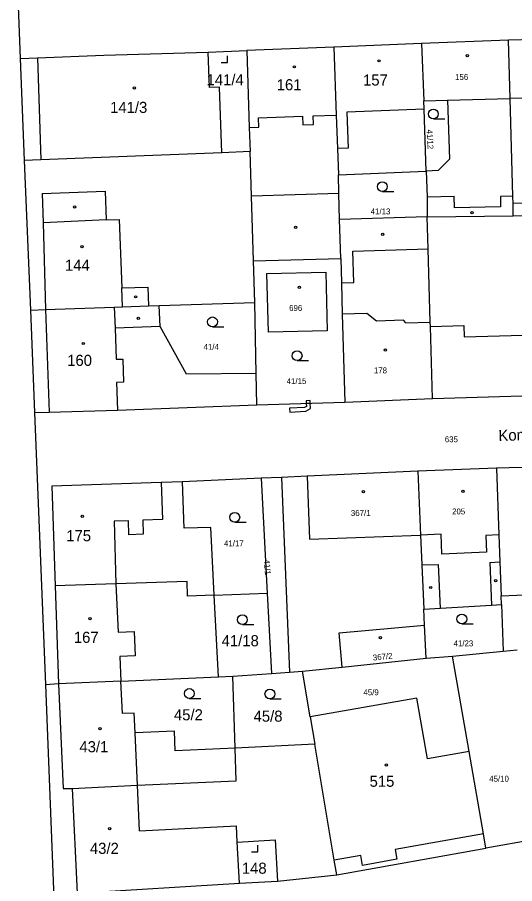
# Model space of a CAD drawing. Extents: x -758582 to -751794, y -998770 to -994350.
# Drawn here: x -755868.7 to -755792.6, y -995731.7 to -995599.1 of the extents above; entities that cross this region are included whole.
import ezdxf

# ---------------------------------------------------------------- set-up
doc = ezdxf.new("R2010")
doc.units = 0
for name, color, linetype in [('Hranice parcel', 7, 'Continuous'), ('Parcelní čísla', 7, 'Continuous'), ('Pop  PČ popisy', 7, 'Continuous'), ('Vnitřní kresba', 7, 'Continuous'), ('Věcná břemena k části', 7, 'Continuous'), ('Značky budov', 7, 'Continuous'), ('Značky kultur', 7, 'Continuous')]:
    doc.layers.add(name, color=color, linetype=linetype)

msp = doc.modelspace()

# ---------------------------------------------------------------- linework, layer by layer
at = {"layer": 'Hranice parcel'}
for p, q in [((-755868.68, -995594.4), (-755868.24, -995605.34)), ((-755793.5, -995602.57), (-755806.84, -995603.06)), ((-755780.18, -995602.19), (-755793.5, -995602.57)), ((-755839.46, -995604.38), (-755833.55, -995604.14)), ((-755820.24, -995603.65), (-755833.55, -995604.14)), ((-755806.84, -995603.06), (-755820.24, -995603.65)), ((-755806.84, -995603.06), (-755806.46, -995611.85)), ((-755868.24, -995605.34), (-755867.61, -995620.96)), ((-755833.06, -995619.62), (-755837.38, -995619.79)), ((-755867.61, -995620.96), (-755866.69, -995643.88)), ((-755819.55, -995623.2), (-755806.1, -995622.61)), ((-755805.96, -995629.63), (-755792.77, -995629.43)), ((-755792.77, -995629.43), (-755784.56, -995629.24)), ((-755805.96, -995629.63), (-755819.36, -995630.03)), ((-755819.19, -995636.01), (-755819.36, -995630.03)), ((-755832.54, -995636.35), (-755819.19, -995636.01)), ((-755832.34, -995642.73), (-755832.54, -995636.35)), ((-755846.95, -995643.2), (-755832.34, -995642.73)), ((-755832.12, -995653.59), (-755832.34, -995642.73)), ((-755866.69, -995643.88), (-755866.06, -995659.58)), ((-755832.02, -995658.39), (-755832.12, -995653.59)), ((-755832.02, -995658.39), (-755818.55, -995658)), ((-755818.55, -995658), (-755805.14, -995657.42)), ((-755866.06, -995659.58), (-755864.39, -995701.24)), ((-755782.88, -995667.7), (-755795.36, -995668.1)), ((-755824.32, -995669.32), (-755828.26, -995669.5)), ((-755807.39, -995668.55), (-755824.32, -995669.32)), ((-755795.36, -995668.1), (-755807.39, -995668.55)), ((-755807.39, -995668.55), (-755806.97, -995678.34)), ((-755831.35, -995669.64), (-755843.39, -995670.19)), ((-755828.26, -995669.5), (-755831.35, -995669.64)), ((-755831.35, -995669.64), (-755830.45, -995687.23)), ((-755828.26, -995669.5), (-755827.02, -995699.31)), ((-755862.9, -995686.1), (-755862.4, -995701.13)), ((-755838.54, -995687.54), (-755830.45, -995687.23)), ((-755837.88, -995700.03), (-755838.54, -995687.54)), ((-755830.45, -995687.23), (-755829.79, -995699.51)), ((-755794.58, -995688.97), (-755794.63, -995687.64)), ((-755794.58, -995688.97), (-755794.31, -995696.13)), ((-755806.1, -995697.2), (-755802.09, -995696.9)), ((-755802.09, -995696.9), (-755794.31, -995696.13)), ((-755799.54, -995711.49), (-755802.09, -995696.9)), ((-755794.31, -995696.13), (-755792.19, -995695.92)), ((-755835.71, -995699.93), (-755829.79, -995699.51)), ((-755829.79, -995699.51), (-755827.02, -995699.31)), ((-755827.02, -995699.31), (-755825.04, -995699.17)), ((-755823.86, -995706.17), (-755825.04, -995699.17)), ((-755862.4, -995701.13), (-755864.39, -995701.24)), ((-755852.83, -995700.7), (-755862.4, -995701.13)), ((-755852.83, -995700.7), (-755837.88, -995700.03)), ((-755837.88, -995700.03), (-755835.71, -995699.93)), ((-755835.35, -995710.94), (-755835.71, -995699.93)), ((-755823.86, -995706.17), (-755823.16, -995710.34)), ((-755823.16, -995710.34), (-755835.35, -995710.94)), ((-755770.99, -995721.69), (-755796.96, -995726.25)), ((-755819.8, -995730.35), (-755796.96, -995726.25)), ((-755834.67, -995731.62), (-755828.88, -995731.31)), ((-755828.88, -995731.31), (-755819.8, -995730.35))]:
    msp.add_line(p, q, dxfattribs=at)
for points in [[(-755792.77, -995629.43), (-755792.79, -995627.57), (-755792.82, -995626.44), (-755793.25, -995611.47), (-755793.5, -995602.57)], [(-755833.55, -995604.14), (-755833.18, -995615.94), (-755833.06, -995619.62)], [(-755820.24, -995603.65), (-755819.86, -995614.02), (-755819.67, -995619.14), (-755819.55, -995623.2)], [(-755868.24, -995605.34), (-755865.58, -995605.25), (-755855.42, -995604.85), (-755839.46, -995604.38)], [(-755837.38, -995619.79), (-755837.74, -995609.74), (-755839.26, -995609.79), (-755839.46, -995604.38)], [(-755806.46, -995611.85), (-755802.82, -995611.75), (-755802.53, -995620.78), (-755804.25, -995622.53), (-755806.1, -995622.61)], [(-755806.1, -995622.61), (-755806.4, -995613.12), (-755806.46, -995611.85)], [(-755837.38, -995619.79), (-755865.08, -995620.88), (-755867.61, -995620.96)], [(-755832.54, -995636.35), (-755832.85, -995626.45), (-755833.06, -995619.62)], [(-755806.1, -995622.61), (-755805.97, -995626.53), (-755805.96, -995629.63)], [(-755819.36, -995630.03), (-755819.47, -995626.04), (-755819.55, -995623.2)], [(-755805.14, -995657.42), (-755805.47, -995646.42), (-755805.49, -995645.72), (-755805.82, -995634.5), (-755805.96, -995629.63)], [(-755819.19, -995636.01), (-755819.08, -995639.69), (-755818.94, -995644.53), (-755818.55, -995658)], [(-755830.26, -995647.29), (-755830.51, -995638.29), (-755821.49, -995638.06), (-755821.26, -995647.05), (-755830.26, -995647.29)], [(-755866.69, -995643.88), (-755864.35, -995643.81), (-755853.85, -995643.44), (-755852.61, -995643.4), (-755848.61, -995643.26), (-755846.95, -995643.2)], [(-755832.12, -995653.59), (-755842.78, -995653.7), (-755846.83, -995646.39), (-755846.95, -995643.2)], [(-755805.14, -995657.42), (-755776.06, -995656.56), (-755772.87, -995656.44)], [(-755866.06, -995659.58), (-755863.8, -995659.5), (-755853.36, -995659.19), (-755832.02, -995658.39)], [(-755824.32, -995669.32), (-755823.96, -995678.98), (-755806.97, -995678.34)], [(-755795.36, -995668.1), (-755794.98, -995678.31), (-755794.82, -995682.45), (-755794.63, -995687.64)], [(-755843.39, -995670.19), (-755846.66, -995670.3), (-755863.41, -995670.84), (-755862.9, -995686.1)], [(-755838.54, -995687.54), (-755839.09, -995677.16), (-755843.14, -995677.29), (-755843.39, -995670.19)], [(-755806.97, -995678.34), (-755806.78, -995682.91), (-755806.49, -995689.68)], [(-755838.54, -995687.54), (-755842.65, -995687.7), (-755842.71, -995685.46), (-755853.59, -995685.79), (-755862.9, -995686.1)], [(-755794.63, -995687.64), (-755792.23, -995687.55), (-755782.12, -995686.92)], [(-755806.49, -995689.68), (-755803.9, -995689.52), (-755796.1, -995689.05), (-755794.58, -995688.97)], [(-755806.1, -995697.2), (-755806.39, -995692.13), (-755806.49, -995689.68)], [(-755825.04, -995699.17), (-755818.95, -995698.57), (-755806.1, -995697.2)], [(-755862.4, -995701.13), (-755861.68, -995717.14), (-755860.28, -995717.12)], [(-755835.35, -995710.94), (-755844.5, -995711.39), (-755844.64, -995708.35), (-755850.67, -995708.62), (-755850.81, -995705.59), (-755852.6, -995705.67), (-755852.83, -995700.7)], [(-755864.39, -995701.24), (-755863.02, -995735.23), (-755860.87, -995744.94)], [(-755799.54, -995711.49), (-755805.93, -995712.61), (-755807.56, -995703.31), (-755823.86, -995706.17)], [(-755819.8, -995730.35), (-755820.18, -995728.09), (-755823.16, -995710.34)], [(-755860.28, -995717.12), (-755850.31, -995716.65), (-755835.18, -995715.95), (-755835.35, -995710.94)], [(-755796.96, -995726.25), (-755797.34, -995724.09), (-755799.54, -995711.49)], [(-755860.28, -995717.12), (-755859.52, -995733.16), (-755834.67, -995731.62)], [(-755834.67, -995731.62), (-755835.01, -995725.33), (-755829.21, -995725.02), (-755828.88, -995731.31)]]:
    msp.add_lwpolyline(points, dxfattribs=at)
at = {"layer": 'Vnitřní kresba'}
for p, q in [((-755865.58, -995605.25), (-755865.08, -995620.88)), ((-755802.82, -995611.75), (-755793.25, -995611.47)), ((-755791.4, -995611.42), (-755793.25, -995611.47)), ((-755806.4, -995613.12), (-755818.24, -995613.56)), ((-755818.24, -995613.56), (-755818.04, -995619.08)), ((-755831.76, -995614.46), (-755825.04, -995614.21)), ((-755831.71, -995615.89), (-755831.76, -995614.46)), ((-755825.04, -995614.21), (-755825, -995615.52)), ((-755823.4, -995614.15), (-755819.86, -995614.02)), ((-755823.35, -995615.46), (-755823.4, -995614.15)), ((-755833.18, -995615.94), (-755831.71, -995615.89)), ((-755825, -995615.52), (-755823.35, -995615.46)), ((-755818.04, -995619.08), (-755819.67, -995619.14)), ((-755864.9, -995626.02), (-755855.23, -995625.68)), ((-755864.9, -995626.02), (-755864.75, -995630.53)), ((-755855.23, -995625.68), (-755855.07, -995630.07)), ((-755819.47, -995626.04), (-755832.85, -995626.45)), ((-755805.97, -995626.53), (-755801.8, -995626.44)), ((-755801.76, -995628.24), (-755801.8, -995626.44)), ((-755792.82, -995626.44), (-755794.75, -995626.48)), ((-755794.75, -995626.48), (-755794.71, -995628.08)), ((-755794.71, -995628.08), (-755801.76, -995628.24)), ((-755785.71, -995627.38), (-755792.79, -995627.57)), ((-755855.07, -995630.07), (-755864.75, -995630.53)), ((-755864.75, -995630.53), (-755864.35, -995643.81)), ((-755855.07, -995630.07), (-755853.07, -995630)), ((-755853.07, -995630), (-755852.71, -995640.5)), ((-755817.31, -995634.84), (-755805.82, -995634.5)), ((-755817.17, -995639.64), (-755817.31, -995634.84)), ((-755819.08, -995639.69), (-755817.17, -995639.64)), ((-755852.71, -995640.5), (-755848.71, -995640.36)), ((-755852.61, -995643.4), (-755852.71, -995640.5)), ((-755848.71, -995640.36), (-755848.61, -995643.26)), ((-755864.35, -995643.81), (-755863.8, -995659.5)), ((-755853.85, -995643.44), (-755853.73, -995646.64)), ((-755815.18, -995644.41), (-755818.94, -995644.53)), ((-755813.69, -995645.58), (-755815.18, -995644.41)), ((-755809.6, -995645.45), (-755813.69, -995645.58)), ((-755809.23, -995645.84), (-755809.6, -995645.45)), ((-755846.83, -995646.39), (-755853.73, -995646.64)), ((-755853.73, -995646.64), (-755853.55, -995651.42)), ((-755809.23, -995645.84), (-755805.49, -995645.72)), ((-755805.47, -995646.42), (-755800.32, -995646.27)), ((-755800.32, -995646.27), (-755800.27, -995647.97)), ((-755800.27, -995647.97), (-755781.38, -995647.41)), ((-755853.55, -995651.42), (-755852.55, -995651.38)), ((-755852.55, -995651.38), (-755852.42, -995654.93)), ((-755852.42, -995654.93), (-755853.52, -995654.97)), ((-755853.52, -995654.97), (-755853.36, -995659.19)), ((-755846.66, -995670.3), (-755846.48, -995675.97)), ((-755851.68, -995676.13), (-755853.88, -995676.19)), ((-755853.88, -995676.19), (-755853.59, -995685.79)), ((-755851.62, -995678.28), (-755851.68, -995676.13)), ((-755846.48, -995675.97), (-755849.48, -995676.06)), ((-755849.48, -995676.06), (-755849.42, -995678.21)), ((-755849.42, -995678.21), (-755851.62, -995678.28)), ((-755803.82, -995678.21), (-755806.97, -995678.34)), ((-755803.69, -995681.25), (-755803.82, -995678.21)), ((-755794.98, -995678.31), (-755796.98, -995678.4)), ((-755796.98, -995678.4), (-755796.87, -995680.96)), ((-755796.87, -995680.96), (-755803.69, -995681.25)), ((-755796.37, -995682.53), (-755794.82, -995682.45)), ((-755796.37, -995682.53), (-755796.1, -995689.05)), ((-755806.78, -995682.91), (-755804.22, -995682.82)), ((-755803.9, -995689.52), (-755804.22, -995682.82)), ((-755853.59, -995685.79), (-755853.25, -995693.22)), ((-755853.25, -995693.22), (-755850.8, -995693.11)), ((-755850.8, -995693.11), (-755850.63, -995696.8)), ((-755819.42, -995693.3), (-755806.39, -995692.13)), ((-755818.95, -995698.57), (-755819.42, -995693.3)), ((-755850.63, -995696.8), (-755853, -995696.91)), ((-755853, -995696.91), (-755852.83, -995700.7)), ((-755850.31, -995716.65), (-755850.67, -995708.62)), ((-755849.99, -995723.6), (-755850.31, -995716.65)), ((-755849.99, -995723.6), (-755835.14, -995722.84)), ((-755835.01, -995725.33), (-755835.14, -995722.84)), ((-755797.34, -995724.09), (-755810.85, -995726.46)), ((-755816.11, -995727.38), (-755820.18, -995728.09)), ((-755815.84, -995728.91), (-755816.11, -995727.38)), ((-755810.85, -995726.46), (-755810.58, -995727.98)), ((-755810.58, -995727.98), (-755815.84, -995728.91))]:
    msp.add_line(p, q, dxfattribs=at)
at = {"layer": 'Věcná břemena k části'}
for points in [[(-755824.45, -995658.17), (-755824.41, -995658.63), (-755824.71, -995658.78), (-755827.01, -995658.91), (-755826.97, -995659.51), (-755824.55, -995659.38), (-755823.79, -995658.97), (-755823.85, -995658.15)], [(-755823.85, -995658.15), (-755823.88, -995657.74), (-755824.48, -995657.76), (-755824.45, -995658.17)]]:
    msp.add_lwpolyline(points, close=True, dxfattribs=at)
at = {"layer": 'Značky budov'}
for centre in [(-755813.31, -995605.72), (-755799.81, -995604.93), (-755826.28, -995606.64), (-755850.77, -995609.88), (-755859.92, -995628.09), (-755799.08, -995628.96), (-755826.09, -995631.21), (-755812.76, -995632.29), (-755858.8, -995634.18), (-755825.5, -995640.41), (-755850.59, -995641.86), (-755850.17, -995645.14), (-755858.6, -995649), (-755812.35, -995650.01), (-755815.72, -995671.68), (-755800.48, -995671.63), (-755858.75, -995675.45), (-755795.48, -995685.3), (-755805.41, -995686.36), (-755857.58, -995691.14), (-755813.12, -995694.05), (-755856.02, -995707.97), (-755812.2, -995713.52), (-755854.54, -995723.28)]:
    msp.add_circle(centre, 0.175, dxfattribs=at)
at = {"layer": 'Značky kultur'}
for p, q in [((-755836.49, -995605.97), (-755836.49, -995604.97)), ((-755837.49, -995605.97), (-755836.49, -995605.97)), ((-755805.01, -995614.61), (-755803.26, -995614.61)), ((-755812.82, -995625.73), (-755811.07, -995625.73)), ((-755838.81, -995646.44), (-755837.06, -995646.44)), ((-755825.86, -995651.62), (-755824.11, -995651.62)), ((-755835.4, -995676.36), (-755833.65, -995676.36)), ((-755834.23, -995692.05), (-755832.48, -995692.05)), ((-755800.65, -995691.94), (-755798.9, -995691.94)), ((-755842.37, -995703.34), (-755840.62, -995703.34)), ((-755830.03, -995703.41), (-755828.28, -995703.41)), ((-755831.86, -995726.83), (-755831.86, -995725.83)), ((-755832.86, -995726.83), (-755831.86, -995726.83))]:
    msp.add_line(p, q, dxfattribs=at)
for centre in [(-755805.01, -995613.86), (-755812.82, -995624.98), (-755838.81, -995645.69), (-755825.86, -995650.87), (-755835.4, -995675.61), (-755834.23, -995691.3), (-755800.65, -995691.19), (-755842.37, -995702.59), (-755830.03, -995702.66)]:
    msp.add_circle(centre, 0.75, dxfattribs=at)

# ---------------------------------------------------------------- texts
at = {"layer": 'Parcelní čísla'}
for s, height, p in [('141/4', 1.7, (-755839.72, -995609.47)), ('157', 1.7, (-755815.77, -995609.51)), ('156', 0.9, (-755801.68, -995608.65)), ('161', 1.7, (-755828.98, -995610.23)), ('141/3', 1.7, (-755854.48, -995613.7)), ('41/13', 0.9, (-755814.6, -995629.23)), ('144', 1.7, (-755861.39, -995637.86)), ('696', 0.9, (-755827.08, -995644.02)), ('41/4', 0.9, (-755840.18, -995649.97)), ('160', 1.7, (-755861.05, -995652.43)), ('178', 0.9, (-755814.11, -995653.57)), ('41/15', 0.9, (-755827.46, -995655.21)), ('635', 0.9, (-755803.26, -995664.12)), ('367/1', 0.9, (-755817.63, -995675.41)), ('205', 0.9, (-755802.14, -995675.17)), ('175', 1.7, (-755861.19, -995679.28)), ('41/17', 0.9, (-755837.05, -995680.06)), ('167', 1.7, (-755860.03, -995694.84)), ('41/18', 1.7, (-755837.41, -995695.36)), ('41/23', 0.9, (-755801.91, -995695.36)), ('45/9', 0.9, (-755815.71, -995702.86)), ('45/2', 1.7, (-755844.71, -995706.7)), ('45/8', 1.7, (-755832.52, -995706.91)), ('43/1', 1.7, (-755859.18, -995711.59)), ('515', 1.7, (-755814.77, -995716.88)), ('45/10', 0.9, (-755796.46, -995716.09)), ('43/2', 1.7, (-755857.57, -995727.15)), ('148', 1.7, (-755834.32, -995730.19))]:
    msp.add_text(s, height=height, dxfattribs=at).set_placement(p)
for s, rotation, p in [('41/12', 273, (-755806.04, -995616.26)), ('41/1', 274, (-755830.94, -995682.12)), ('367/2', 6, (-755814.22, -995697.56))]:
    msp.add_text(s, height=0.9, rotation=rotation, dxfattribs=at).set_placement(p)
at = {"layer": 'Pop  PČ popisy'}
msp.add_text('Komenského', height=1.7, rotation=2, dxfattribs=at).set_placement((-755795.02, -995663.95))

doc.saveas('drawing.dxf')
